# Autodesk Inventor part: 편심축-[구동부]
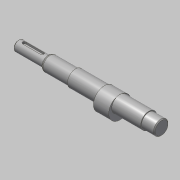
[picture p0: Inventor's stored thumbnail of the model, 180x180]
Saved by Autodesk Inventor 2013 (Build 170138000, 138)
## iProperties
Created: 2017-08
Part Number: 편심축-[구동부]
Material: 강철, 연강
Document SubType Name: Modeling
Designer: mduedu
Density: 7.86 g/cm^3
Mass: 338.399 g
Surface Area: 105.4 cm^2
Volume: 43.0533 cm^3
Author: mduedu
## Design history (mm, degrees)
sketch "스케치1"
  geometry: L1 (0, 0)-(168, 0); L2 (168, 0)-(168, 8.5); L3 (168, 8.5)-(153, 8.5); L4 (153, 8.5)-(153, 9.5); L5 (153, 9.5)-(67, 9.5); L6 (67, 9.5)-(67, 8.5); L7 (67, 8.5)-(35, 8.5); L8 (35, 8.5)-(35, 6); L9 (35, 6)-(0, 6); L10 (0, 6)-(0, 0)
  constraints: 20 end point, 6 parallel, 2 collinear, 2 perpendicular, 1 horizontal
  dimensions: "d0" = 168 distance of L1.start L1.end; "d1" = 17 diameter of L3 L1; "d2" = 19 diameter of L5 L1; "d3" = 12 diameter of L9 L1; "d4" = 35 distance of L8.end L9.end; "d5" = 15 distance of L2.end L3.end; "d6" = 86 distance of L4.end L5.end
revolve "회전1" sketch "스케치1" stored, may be unused: angle "d7" = 90 deg
node "작업 평면1"
sketch "스케치2"
  geometry: C1 r 9.5 at (0, 0) reference; C2 r 13 at (0, -3.5); 1 further point
  constraints: 1 centre point, 1 tangent, 1 vertical alignment
  dimensions: "d8" = 3.5 distance of point (0, 0) C2.centre
extrude "돌출1" join sketch "스케치2" stored distance "d9" = 18; taper "d10" = 0 deg
chamfer "모따기1" distance "d11" = 1; stored, may be unused: second distance "d12" = 2, angle "d13" = 45 deg
node "작업 평면2"
sketch "스케치3"
  geometry: L1 (10.5, -2)-(-10.5, -2); L2 (-10.5, -2)-(-10.5, 2); L3 (-10.5, 2)-(10.5, 2); L4 (10.5, 2)-(10.5, -2); L5 (17.5, 6)-(17.5, -6) reference; L6 (-17.5, 8.5)-(-17.5, -8.5) reference; A1 r 2 centre (10.5, 0) between (10.5, -2) and (10.5, 2); A2 r 2 centre (-10.5, 0) between (-10.5, 2) and (-10.5, -2); A3 r 2 centre (10.5, 0) between (10.5, 2) and (10.5, -2); A4 r 2 centre (-10.5, 0) between (-10.5, -2) and (-10.5, 2); 1 further point
  constraints: 8 end point, 8 point on circle, 4 centre point, 2 midpoint, 2 parallel, 1 horizontal, 1 horizontal alignment, 1 perpendicular
  dimensions: "d14" = 25 dimension on A2 A1; "d16" = 4 distance between parallel lines of L3 L1; "d17" = 5 distance edge to line of A1 L5; "d46" = 5 distance edge to line of A2 L6 (derived)
extrude "돌출2" cut sketch "스케치3" distance "d18" = 2.5; taper "d19" = 0 deg
chamfer "모따기2" distance "d20" = 1; stored, may be unused: second distance "d21" = 2, angle "d22" = 45 deg
chamfer "모따기4" distance "d39" = 1.82; stored, may be unused: second distance "d40" = 2, angle "d41" = 30 deg
fillet "모깎기4" dims "d45" = 2
hole "구멍1" diameter "d29" = 3.242; stored, may be unused: countersink angle "d33" = 90 deg, drill point angle "d35" = 118 deg; dims "d30" = 8, "d31" = 4, "d32" = 2, "d34" = 10, "d36" = 10, "d37" = 10
node "솔리드1"
node "절단 모서리 투영1"
